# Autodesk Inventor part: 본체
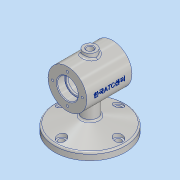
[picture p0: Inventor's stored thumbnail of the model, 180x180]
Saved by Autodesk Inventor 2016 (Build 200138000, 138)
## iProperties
Created: 2018-12
Part Number: 본체
Material: 알루미늄 6061
Document SubType Name: Modeling
Designer: 605-03
Density: 2.7 g/cm^3
Appearance: 알루미늄 - 평지
Mass: 684.83 g
Surface Area: 556.057 cm^2
Volume: 253.641 cm^3
Author: 605-03
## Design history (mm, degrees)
sketch "스케치2"
  geometry: C1 r 30 at (0, 0); 1 further point
  constraints: 1 centre point, 1 coincident
  dimensions: "d0" = 60 diameter of C1
extrude "돌출1" new body sketch "스케치2" stored distance "d1" = 70; taper "d2" = 0 deg
node "작업 평면1"
sketch "스케치3"
  geometry: C1 r 55 at (0, 0); 1 further point
  constraints: 1 centre point, 1 coincident
  dimensions: "d4" = 110 diameter of C1
extrude "돌출2" join sketch "스케치3" distance "d5" = 11; taper "d6" = 0 deg
sketch "스케치5"
  geometry: L1 (55, -75)-(55, -64) reference; L2 (55, -64)-(-55, -64) reference; L3 (55, -64)-(0, -49.263); L4 (0, -49.263)-(0, -64); L5 (0, -64)-(55, -64); 1 further point
  constraints: 6 end point, 1 collinear, 1 midpoint, 1 vertical alignment
  dimensions: "d10" = 75 deg angle of L3 L1
revolve "회전1" sketch "스케치5" stored, may be unused: angle "d11" = 90 deg
sketch "스케치6"
  geometry: C1 r 12 at (0, 0); 1 further point
  constraints: 1 centre point, 1 coincident
  dimensions: "d12" = 24 diameter of C1
extrude "돌출4" join sketch "스케치6" stored distance "d13" = 37; taper "d14" = 0 deg
sketch "스케치7"
  geometry: C1 r 10 at (0, 0); 1 further point
  constraints: 1 centre point, 1 coincident
  dimensions: "d15" = 20 diameter of C1
extrude "돌출5" join sketch "스케치7" distance "d16" = 37; taper "d17" = 0 deg
fillet "모깎기1" dims "d18" = 3
fillet "모깎기2" dims "d19" = 3
sketch "스케치8"
  geometry: L1 (-35, 16)-(-23, 16); L2 (-23, 16)-(-23, 14); L3 (-23, 14)-(-20, 14); L4 (-20, 14)-(-20, 25); L5 (-20, 25)-(20, 25); L6 (20, 25)-(20, 14); L7 (20, 14)-(23, 14); L8 (23, 14)-(23, 16); L9 (23, 16)-(35, 16); L10 (-35, 30)-(-35, -30) reference; L11 (35, -30)-(35, 30) reference; L12 (-35, 0)-(35, 0); L13 (-35, 16)-(-35, 0); L14 (35, 16)-(35, 0); 1 further point
  constraints: 24 end point, 7 perpendicular, 2 midpoint, 2 parallel, 2 point on line, 1 collinear, 1 horizontal
  dimensions: "d20" = 16 distance from line of point (0, 0) L1; "d21" = 12 distance of L1.start L1.end; "d22" = 14 distance from line of point (0, 0) L3; "d23" = 3 distance of L2.end L3.end; "d24" = 25 distance from line of point (0, 0) L5; "d25" = 40 distance of L4.end L5.end; "d26" = 14 distance from line of point (0, 0) L7; "d27" = 3 distance of L6.end L7.end; "d28" = 16 distance from line of point (0, 0) L9
revolve "회전2" sketch "스케치8" stored, may be unused: angle "d29" = 90 deg
fillet "모깎기3" dims "d30" = 0.3
fillet "모깎기4" dims "d31" = 0.3
chamfer "모따기1" distance "d32" = 1; stored, may be unused: second distance "d33" = 2, angle "d34" = 45 deg
fillet "모깎기5" dims "d35" = 3
sketch "스케치9"
  geometry: C1 r 30 at (0, 0) reference; 1 further point
  constraints: 1 vertical alignment
  dimensions: "d36" = 23 distance of C1.centre point (0, 23)
hole "구멍1" sketch "스케치9" at (0, 23) diameter "d37" = 3.459; stored, may be unused: countersink angle "d41" = 90 deg, drill point angle "d43" = 118 deg; dims "d38" = 8, "d39" = 4, "d40" = 2, "d42" = 10
sketch "스케치12"
  geometry: C1 r 10 at (0, 0) reference
hole "구멍2" sketch "스케치12" at (0, 0) diameter "d47" = 10; stored, may be unused: countersink angle "d51" = 90 deg, drill point angle "d53" = 118 deg; dims "d48" = 8, "d49" = 4, "d50" = 2, "d52" = 40
chamfer "모따기2" distance "d54" = 1; stored, may be unused: second distance "d55" = 2, angle "d56" = 45 deg
sketch "스케치15"
  geometry: C1 r 55 at (0, 0) reference; 1 further point
  constraints: 1 vertical alignment
  dimensions: "d66" = 44 distance of C1.centre point (0, -44)
hole "구멍4" sketch "스케치15" at (0, -44) diameter "d67" = 9; stored, may be unused: countersink angle "d71" = 90 deg, drill point angle "d73" = 0 deg; dims "d68" = 8, "d69" = 14, "d70" = 3, "d72" = 10
sketch "스케치17"
  geometry: C1 r 4.5 at (0, 0) reference; C2 r 7 at (0, 0); 1 further point
  constraints: 1 centre point, 1 coincident
  dimensions: "d75" = 14 diameter of C2
extrude "돌출6" cut sketch "스케치17" stored distance "d76" = 37; taper "d77" = 0 deg
node "작업 평면4"
sketch "스케치18"
  geometry: L1 (-35, 30)-(35, 30) reference; L2 (-35, 30)-(-35, -30) reference; 2 further points
  constraints: 1 other
  dimensions: "d81" = 30 distance from line of point (0, 0) L1
feature "엠보싱1" sketch "스케치18" dims "d2" = 0, "d82" = 0.5, "d83" = 0
node "솔리드1"
pattern_circular "원형 패턴1" dims angle "d45" = 360 deg
mirror "대칭1"
pattern_circular "원형 패턴2" dims angle "d79" = 360 deg
other parameters: "d3" = -75
